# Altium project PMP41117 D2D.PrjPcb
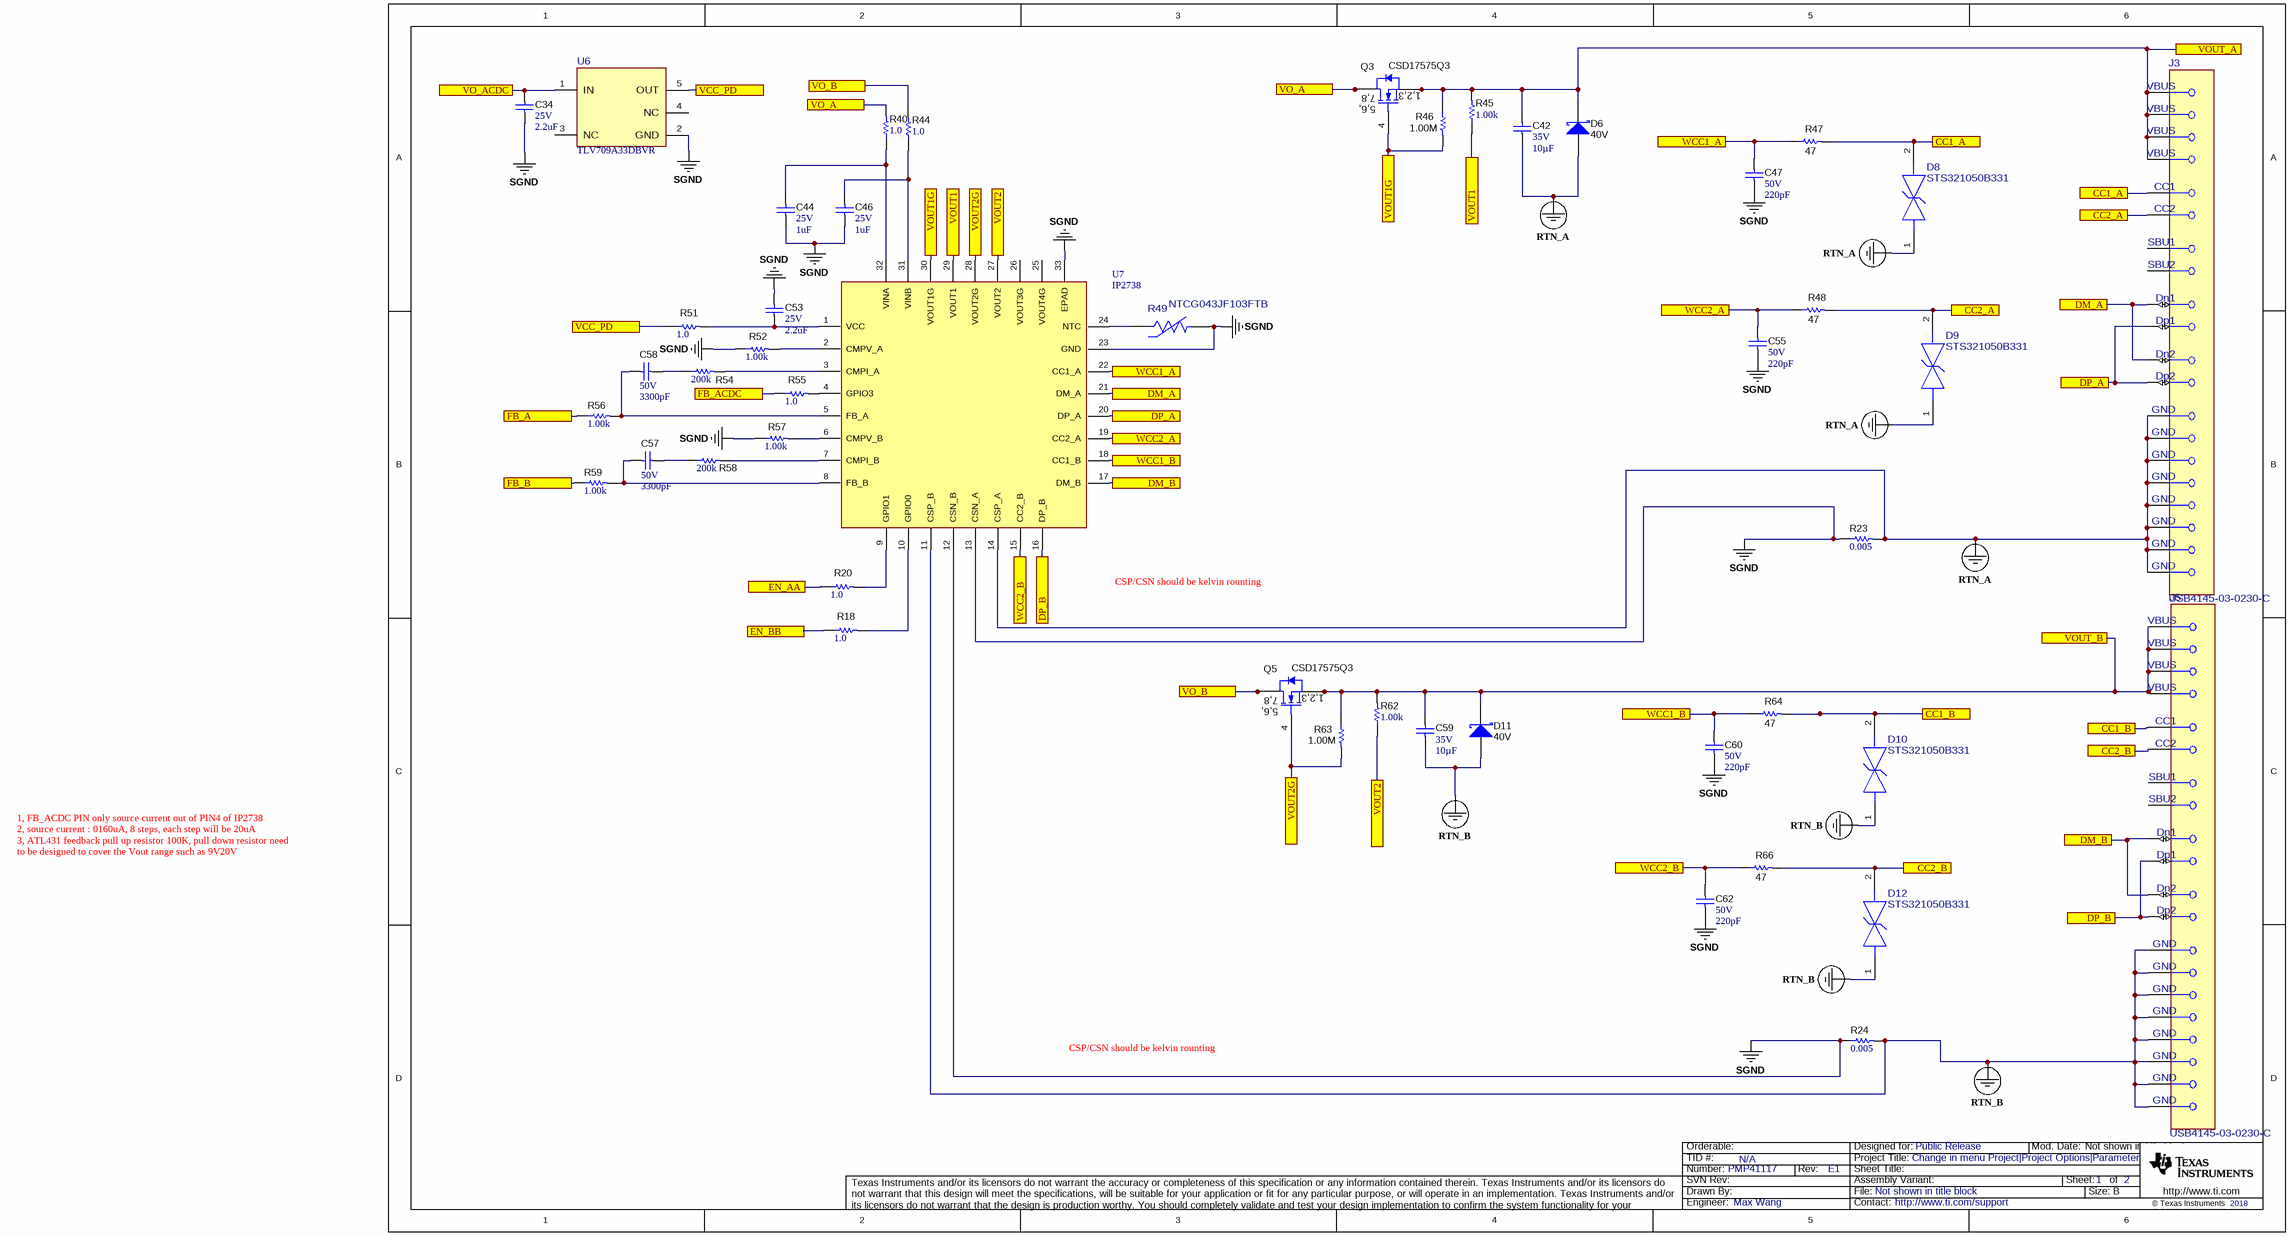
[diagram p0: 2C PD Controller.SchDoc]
CopyrightYear: 2018; PCB_Layout: Max Wang; PCB_Rev: E1; PRJ_Customer: Public Release; PRJ_Engineer: Max Wang; PRJ_Number: PMP41117; PRJ_Title: Change in menu Project|Project Options|Parameters; SCH_Rev: E1; TechSupport: http://www.ti.com/support; TID: N/A
2 sheets, 79 parts. Net scope: flat (ports and power ports of the same name join across sheets).
Board file: PMP41117 DCDC.PcbDoc
Sheets:
  2C PD Controller.SchDoc
  Dual Port DCDC.SchDoc

## Sheet 2C PD Controller.SchDoc
size 431 x 279 mm; Date: Not shown in title block; ApprovedBy: Not shown in title block; CheckedBy: Not shown in title block; Author: Not shown in title block; CompanyName: Not shown in title block; Engineer: Not shown in title block; Organization: Not shown in title block; Address1: Not shown in title block; Address2: Not shown in title block; Address3: Not shown in title block; Address4: Not shown in title block; DocumentNumber: 1; Revision: Use project parameter SCH_Rev; SheetNumber: 1; SheetTotal: 2; PageSetup: Record=PageOptions¦CenterHorizontal=True¦CenterVertical=True¦PrintScale=1.00¦XCorrection=1.00¦YCorrection=1.00¦PrintKind=0¦BorderSize=5000000¦LeftOffset=0¦BottomOffset=0¦Orientation=2¦PaperLength=1000¦PaperWidth=1000¦Scale=100¦PaperSource=15¦PrintQuality=600¦MediaType=1¦DitherType=10¦PaperKind=Letter¦PrintScaleMode=1

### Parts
C34  VDC_V: 25V  ValueDisplayed: 2.2uF  [0402_070]  (hidden comment: GRM155R61E225KE11D)
C42  VDC_V: 35V  ValueDisplayed: 10µF  [0805]  (hidden comment: GMK212BBJ106KG-T)
C44  VDC_V: 25V  ValueDisplayed: 1uF  [0402S]  (hidden comment: GRM155R61E105KA12D)
C46  VDC_V: 25V  ValueDisplayed: 1uF  [0402S]  (hidden comment: GRM155R61E105KA12D)
C47  VDC_V: 50V  ValueDisplayed: 220pF  [0402S]  (hidden comment: GRM155R71H221KA01D)
C53  VDC_V: 25V  ValueDisplayed: 2.2uF  [0402_070]  (hidden comment: GRM155R61E225KE11D)
C55  VDC_V: 50V  ValueDisplayed: 220pF  [0402S]  (hidden comment: GRM155R71H221KA01D)
C57  VDC_V: 50V  ValueDisplayed: 3300pF  [0402S]  (hidden comment: CGA2B2X7R1H332K050BA)
C58  VDC_V: 50V  ValueDisplayed: 3300pF  [0402S]  (hidden comment: CGA2B2X7R1H332K050BA)
C59  VDC_V: 35V  ValueDisplayed: 10µF  [0805]  (hidden comment: GMK212BBJ106KG-T)
C60  VDC_V: 50V  ValueDisplayed: 220pF  [0402S]  (hidden comment: GRM155R71H221KA01D)
C62  VDC_V: 50V  ValueDisplayed: 220pF  [0402S]  (hidden comment: GRM155R71H221KA01D)
D6  value 40V  [SOD-523]  (hidden comment: RB521SM-40T2R)
D8  STS321050B331  [FP-STS321050B331_SOD-323-MFG]
D9  STS321050B331  [FP-STS321050B331_SOD-323-MFG]
D10  STS321050B331  [FP-STS321050B331_SOD-323-MFG]
D11  value 40V  [SOD-523]  (hidden comment: RB521SM-40T2R)
D12  STS321050B331  [FP-STS321050B331_SOD-323-MFG]
J3  USB4145-03-0230-C  [FP-USB4145-03-0230-C_CONN_USB-MFG]
J5  USB4145-03-0230-C  [FP-USB4145-03-0230-C_CONN_USB-MFG]
Q3  CSD17575Q3  [DQG0008A]
Q5  CSD17575Q3  [DQG0008A]
R18  ValueDisplayed: 1.0  [0402S]  (hidden comment: CRCW04021R00JNED)
R20  ValueDisplayed: 1.0  [0402S]  (hidden comment: CRCW04021R00JNED)
R23  ValueDisplayed: 0.005  [WSL0805]  (hidden comment: WSL08055L000FEA)
R24  ValueDisplayed: 0.005  [WSL0805]  (hidden comment: WSL08055L000FEA)
R40  ValueDisplayed: 1.0  [0402S]  (hidden comment: CRCW04021R00JNED)
R44  ValueDisplayed: 1.0  [0402S]  (hidden comment: CRCW04021R00JNED)
R45  ValueDisplayed: 1.00k  [0402S]  (hidden comment: MCR01MZPF1001)
R46  ValueDisplayed: 1.00M  [0402S]  (hidden comment: RMCF0402FT1M00)
R47  ValueDisplayed: 47  [0402S]  (hidden comment: CRCW040247R0JNED)
R48  ValueDisplayed: 47  [0402S]  (hidden comment: CRCW040247R0JNED)
R49  NTCG043JF103FTB  [FP-NTCG043JF103FTB_SMD2-MFG]
R51  ValueDisplayed: 1.0  [0402S]  (hidden comment: CRCW04021R00JNED)
R52  ValueDisplayed: 1.00k  [0402S]  (hidden comment: MCR01MZPF1001)
R54  ValueDisplayed: 200k  [0402S]  (hidden comment: CRCW0402200KFKED)
R55  ValueDisplayed: 1.0  [0402S]  (hidden comment: CRCW04021R00JNED)
R56  ValueDisplayed: 1.00k  [0402S]  (hidden comment: MCR01MZPF1001)
R57  ValueDisplayed: 1.00k  [0402S]  (hidden comment: MCR01MZPF1001)
R58  ValueDisplayed: 200k  [0402S]  (hidden comment: CRCW0402200KFKED)
R59  ValueDisplayed: 1.00k  [0402S]  (hidden comment: MCR01MZPF1001)
R62  ValueDisplayed: 1.00k  [0402S]  (hidden comment: MCR01MZPF1001)
R63  ValueDisplayed: 1.00M  [0402S]  (hidden comment: RMCF0402FT1M00)
R64  ValueDisplayed: 47  [0402S]  (hidden comment: CRCW040247R0JNED)
R66  ValueDisplayed: 47  [0402S]  (hidden comment: CRCW040247R0JNED)
U6  TLV709A33DBVR  [DBV0005A-MFG]
U7  IP2738  [IP2738]

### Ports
CC1_A, CC1_B, CC2_A, CC2_B, DM_A, DM_B, DP_A, DP_B, EN_AA, EN_BB, FB_A, FB_ACDC, FB_B, VCC_PD, VO_A, VO_ACDC, VO_B, VOUT1, VOUT1G, VOUT2, VOUT2G, VOUT_A, VOUT_B, WCC1_A, WCC1_B, WCC2_A, WCC2_B

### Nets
RTN_A: C42.2 D6.2(A) D8.1 D9.1 J3.1(GND) J3.2(GND) J3.3(GND) J3.4(GND) J3.A1(GND) J3.A12(GND) J3.B1(GND) J3.B12(GND) R23.2 U7.14(CSP_A)
RTN_B: C59.2 D10.1 D11.2(A) D12.1 J5.1(GND) J5.2(GND) J5.3(GND) J5.4(GND) J5.A1(GND) J5.A12(GND) J5.B1(GND) J5.B12(GND) R24.2 U7.11(CSP_B)
SGND: C34.2 C44.2 C46.2 C47.2 C53.1 C55.2 C60.2 C62.2 R23.1 R24.1 R49.2 R52.1 R57.1 U6.2(GND) U7.12(CSN_B) U7.13(CSN_A) U7.23(GND) U7.33(EPAD)
CC1_A: D8.2 J3.A5(CC1) R47.2 ; port CC1_A
CC1_B: D10.2 J5.A5(CC1) R64.2 ; port CC1_B
CC2_A: D9.2 J3.B5(CC2) R48.2 ; port CC2_A
CC2_B: D12.2 J5.B5(CC2) R66.2 ; port CC2_B
DM_A: J3.A7(Dn1) J3.B7(Dn2) U7.21(DM_A) ; port DM_A
DM_B: J5.A7(Dn1) J5.B7(Dn2) U7.17(DM_B) ; port DM_B
DP_A: J3.A6(Dp1) J3.B6(Dp2) U7.20(DP_A) ; port DP_A
DP_B: J5.A6(Dp1) J5.B6(Dp2) U7.16(DP_B) ; port DP_B
EN_AA: R20.1 ; port EN_AA
EN_BB: R18.1 ; port EN_BB
FB_A: R56.1 ; port FB_A
FB_ACDC: R55.1 ; port FB_ACDC
FB_B: R59.1 ; port FB_B
VCC_PD: R51.1 U6.5(OUT) ; port VCC_PD
VO_A: Q3.5(D) Q3.6(D) Q3.7(D) Q3.8(D) Q3.9(D) R40.2 ; port VO_A
VO_ACDC: C34.1 U6.1(IN) ; port VO_ACDC
VO_B: Q5.5(D) Q5.6(D) Q5.7(D) Q5.8(D) Q5.9(D) R44.2 ; port VO_B
VOUT1: R45.1 U7.29(VOUT1) ; port VOUT1
VOUT1G: Q3.4(G) R46.2 U7.30(VOUT1G) ; port VOUT1G
VOUT2: R62.1 U7.27(VOUT2) ; port VOUT2
VOUT2G: Q5.4(G) R63.2 U7.28(VOUT2G) ; port VOUT2G
VOUT_A: C42.1 D6.1(K) J3.A4(VBUS) J3.A9(VBUS) J3.B4(VBUS) J3.B9(VBUS) Q3.1(S) Q3.2(S) Q3.3(S) R45.2 R46.1 ; port VOUT_A
VOUT_B: C59.1 D11.1(K) J5.A4(VBUS) J5.A9(VBUS) J5.B4(VBUS) J5.B9(VBUS) Q5.1(S) Q5.2(S) Q5.3(S) R62.2 R63.1 ; port VOUT_B
WCC1_A: C47.1 R47.1 U7.22(CC1_A) ; port WCC1_A
WCC1_B: C60.1 R64.1 U7.18(CC1_B) ; port WCC1_B
WCC2_A: C55.1 R48.1 U7.19(CC2_A) ; port WCC2_A
WCC2_B: C62.1 R66.1 U7.15(CC2_B) ; port WCC2_B
NetC44_1: C44.1 R40.1 U7.32(VINA)
NetC46_1: C46.1 R44.1 U7.31(VINB)
NetC53_2: C53.2 R51.2 U7.1(VCC)
NetC57_1: C57.1 R58.1
NetC57_2: C57.2 R59.2 U7.8(FB_B)
NetC58_1: C58.1 R54.1
NetC58_2: C58.2 R56.2 U7.5(FB_A)
NetR18_2: R18.2 U7.10(GPIO0)
NetR20_2: R20.2 U7.9(GPIO1)
NetR49_1: R49.1 U7.24(NTC)
NetR52_2: R52.2 U7.2(CMPV_A)
NetR54_2: R54.2 U7.3(CMPI_A)
NetR55_2: R55.2 U7.4(GPIO3)
NetR57_2: R57.2 U7.6(CMPV_B)
NetR58_2: R58.2 U7.7(CMPI_B)

Not connected (* = marked no-connect by the designer): J3 A8(SBU1) B8(SBU2); J5 A8(SBU1) B8(SBU2); U6 3(NC) 4(NC); U7 25(VOUT4G) 26(VOUT3G)

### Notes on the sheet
- CSP/CSN should be kelvin rounting
- 1, FB_ACDC PIN only source current out of PIN4 of IP2738
  2, source current : 0160uA, 8 steps, each step will be 20uA
  3, ATL431 feedback pull up resistor 100K, pull down resistor need to be designed to cover the Vout range such as 9V20V

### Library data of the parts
C34 C53 = CMP-0006610-2: CAP, CERM, 2.2 uF, 25 V, +/- 10%, X5R, 0402; Manufacturer: MuRata; TaMin_C: -55°C; Polarized: N; SizeAreaWB_mm2: 3; Value1: Unknown; U/M: EA; Value: 2.2uF; TaMax_C: 85°C; SizeZ_mm: 0.7; SizeX_mm: 1; SizeY_mm: 0.5; Cap_Case: 0402; Cap_F: 2.2µF; AEC Category: Q200
C42 C59 = CMP-0083708-1: CAP, CERM, 10 µF, 35 V,+/- 10%, X5R, 0805; Manufacturer: Taiyo Yuden; SizeAreaWB_mm2: 6.75; SizeArea_mm2: 2.5; AEC Qualified: N; AEC Category: Q200; Value: 10uF; TaMax_C: 85°C; SizeZ_mm: 1.45; TaMin_C: -55°C; SizeY_mm: 1.25; U/M: EA; SizeX_mm: 2
C44 C46 = CMP-0006608-2: CAP, CERM, 1 uF, 25 V, +/- 10%, X5R, 0402; Manufacturer: MuRata; TaMin_C: -55°C; Polarized: N; SizeAreaWB_mm2: 3; Value1: Unknown; U/M: EA; Value: 1uF; TaMax_C: 85°C; SizeZ_mm: 0.6; SizeX_mm: 1; SizeY_mm: 0.5; Cap_Case: 0402; Cap_F: 1µF; AEC Category: Q200
C47 C55 C60 C62 = CMP-0006682-1: CAP, CERM, 220 pF, 50 V, +/- 10%, X7R, 0402; Manufacturer: MuRata; TaMin_C: -55°C; Polarized: N; SizeAreaWB_mm2: 3; Value1: Unknown; U/M: EA; Value: 220pF; TaMax_C: 125°C; SizeZ_mm: 0.6; SizeX_mm: 1; SizeY_mm: 0.5; Cap_Case: 0402; AEC Category: Q200
C57 C58 = CMP-0006319-1: CAP, CERM, 3300 pF, 50 V, +/- 10%, X7R, AEC-Q200 Grade 1, 0402; Manufacturer: TDK; TaMin_C: -55°C; ESR_ohm: 0.7852; Polarized: N; SizeAreaWB_mm2: 3; Value1: 0.785178 ohm; U/M: EA; Value: 3300pF; TaMax_C: 125°C; SizeZ_mm: 0.6; SizeX_mm: 1; SizeY_mm: 0.5; Cap_Case: 0402; AEC Qualified: Y; Cap_F: 3.3nF; IRMS_A: 272.902mA; AEC Category: Q200
D6 D11 = CMP-0074704-3: Diode, Schottky, 40 V, 0.2 A, SOD-523; Manufacturer: Rohm; SizeAreaWB_mm2: 5.13; SizeZ_mm: 0.65; AEC Category: Q101; AEC Qualified: N; Vf_V: 540mV; Io_A: 200mA; Value2: 0.54V; SizeArea_mm2: 1.53; TJmax_C: 150°C; Value1: 0.2A; SizeX_mm: 1.7; SizeY_mm: 0.9
D8-D10 D12 = CMP-0092592-1: 18V Clamp 22A (8/20µs) Ipp Tvs Diode Surface Mount SOD-323; Manufacturer: Eaton; ValueDisplayed: 33pF; Breakdown Voltage: 5.5V; Number Of Channels: 1; SizeZ_mm: 1mm; AEC Qualified: No; Ppk: 400W; VRWM: 5V; TJmax_C: +125°C; Direction: Bidirectional
J3 J5 = CMP-0120965-1: USB Connectors USB-C Rec 3u Vert 16P SMT 2.3mm TH stakes H7.46mm T+R+Cap; Manufacturer: GCT; ContactFinish: Gold,Nickel; Current_A: 6.25A; Shrouded: true; Voltage_V: 48V; AEC Qualified: No; Conn Orientation: Vertical; DUT-Pitch_mm: 0.5mm; Is Female: yes; SizeZ_mm: 7.66mm; Standoff Height: 0.05mm; Usb Standard: USB 2.0
Q3 Q5 = MOSFET_N_D56789G4S123: MOSFET, N-CH, 30 V, 60 A, DQG0008A (VSON-CLIP-8); Manufacturer: Texas Instruments; Alternate Manufacturer: None; U/M: EA; ChType: N; Value: 30V; Value1: 0.003; Rdson45_ohm: 3.2m; Value2: 23 nC; QgTyp_nC: 23; Vgs_V: 20V; IdsMax_A: 60A; AEC Category: Q101; SizeZ_mm: 1.1; SizeX_mm: 3.3; SizeArea_mm2: 10.89; SizeAreaWB_mm2: 18.49
R18 R20 R40 R44 R51 R55 = CMP-0026866-2: RES, 1.0, 5%, 0.063 W, 0402; Manufacturer: Vishay-Dale; Power_W: 63mW; TempCo: 200 ppm/C; Value_Code: 1R00; U/M: EA; Value: 1.0; EIA_Code: E24; Res_ohm: 1; SizeY_mm: 0.5; SizeZ_mm: 0.6; Value2: 0.063W; VDC_V: 50V; AEC Category: Q200
R23 R24 = CMP-0021978-2: RES, 0.005, 1%, 0.25 W, 0805; Manufacturer: Vishay-Dale; Power_W: 250mW; TempCo: 110 ppm/C; Value_Code: 5L000; U/M: EA; Value: 0.005; EIA_Code: E96; Res_ohm: 5m; SizeX_mm: 2.03; SizeY_mm: 1.27; SizeZ_mm: 0.584; Value2: 0.25W; SizeArea_mm2: 2.5781; AEC Qualified: N; AEC Category: Q200
R45 R52 R56 R57 R59 R62 = CMP-0026716-1: RES, 1.00 k, 1%, 0.063 W, 0402; Manufacturer: Rohm; Power_W: 63mW; TempCo: 100 ppm/C; Value_Code: 1k00; U/M: EA; Value: 1.00k; EIA_Code: E96; Res_ohm: 1k; SizeX_mm: 1; SizeY_mm: 0.5; SizeZ_mm: 0.6; Value2: 0.063W; AEC Qualified: N; VDC_V: 50V; AEC Category: Q200
R46 R63 = CMP-0026827-3: RES, 1.00 M, 1%, 0.063 W, AEC-Q200 Grade 0, 0402; Manufacturer: Stackpole Electronics Inc; CompType: Resistor; Value: 1.0Meg; Power_W: 63mW; Value2: 0.063W; VDC_V: 50V; TempCo: 200 ppm/C; SizeArea_mm2: 0.5; SizeX_mm: 1; SizeZ_mm: 0.6; EIA_Code: E24; AEC Category: Q200; AEC Qualified: Y; AEC Grade: 0
R47 R48 R64 R66 = CMP-0026463-2: RES, 47, 5%, 0.063 W, 0402; Manufacturer: Vishay-Dale; Power_W: 63mW; TempCo: 200 ppm/C; Value: 47; EIA_Code: E96; SizeX_mm: 1; SizeY_mm: 0.5; SizeZ_mm: 0.6; Value2: 0.063W; AEC Qualified: Y; VDC_V: 50V; AEC Category: Q200; AEC Grade: 0
R49 = CMP-0095068-1: Chip NTC Thermistors (Sensor), Resistance (at 25°C)=10kΩ, Resistance Tolerance (at 25°C)=±1%; Manufacturer: TDK; SizeZ_mm: 0.22mm; B 25 50: 3380K; Value: 10k; B Tolerance: 1%; B 25 100: 3453K; Res_ohm: 10kΩ; B 25 85: 3435K; AEC Qualified: No
R54 R58 = CMP-0026158-1: RES, 200 k, 1%, 0.063 W, 0402; Manufacturer: Vishay-Dale; Power_W: 63mW; TempCo: 100 ppm/C; U/M: EA; Value: 200k; EIA_Code: E96; SizeX_mm: 1; SizeY_mm: 0.5; SizeZ_mm: 0.6; Value2: 0.063W; VDC_V: 50V; AEC Category: Q200
U6 = CMP-0034271-1: 150-mA 30-V low-dropout (LDO) linear regulator with 3.2-μA supply current 5-SOT-23 -40 to 125; Manufacturer: Texas Instruments; SizeZ_mm: 1.45mm; AEC Qualified: No; Accuracy Percentage: 4%; Dropout Voltage: 1000mV; Max Supply Voltage: 30V; Min Supply Voltage: 4.3V; Nominal Supply Current: 3.2uA; Number Of Outputs: 1; Output Type: Fixed; Output Voltage: 3.3V; Standoff Height: 0mm; TJmax_C: +125°C
U7 = U?: IP2738 dual port USB PD controller; Manufacturer: Injonics

## Sheet Dual Port DCDC.SchDoc
size 431 x 279 mm; Date: Not shown in title block; ApprovedBy: Not shown in title block; CheckedBy: Not shown in title block; Author: Not shown in title block; CompanyName: Not shown in title block; Engineer: Not shown in title block; Organization: Not shown in title block; Address1: Not shown in title block; Address2: Not shown in title block; Address3: Not shown in title block; Address4: Not shown in title block; DocumentNumber: 2; Revision: Use project parameter SCH_Rev; SheetNumber: 2; SheetTotal: 2; PageSetup: Record=PageOptions¦CenterHorizontal=True¦CenterVertical=True¦PrintScale=1.00¦XCorrection=1.00¦YCorrection=1.00¦PrintKind=0¦BorderSize=5000000¦LeftOffset=0¦BottomOffset=0¦Orientation=2¦PaperLength=1000¦PaperWidth=1000¦Scale=100¦PaperSource=15¦PrintQuality=600¦MediaType=1¦DitherType=10¦PaperKind=Letter¦PrintScaleMode=1
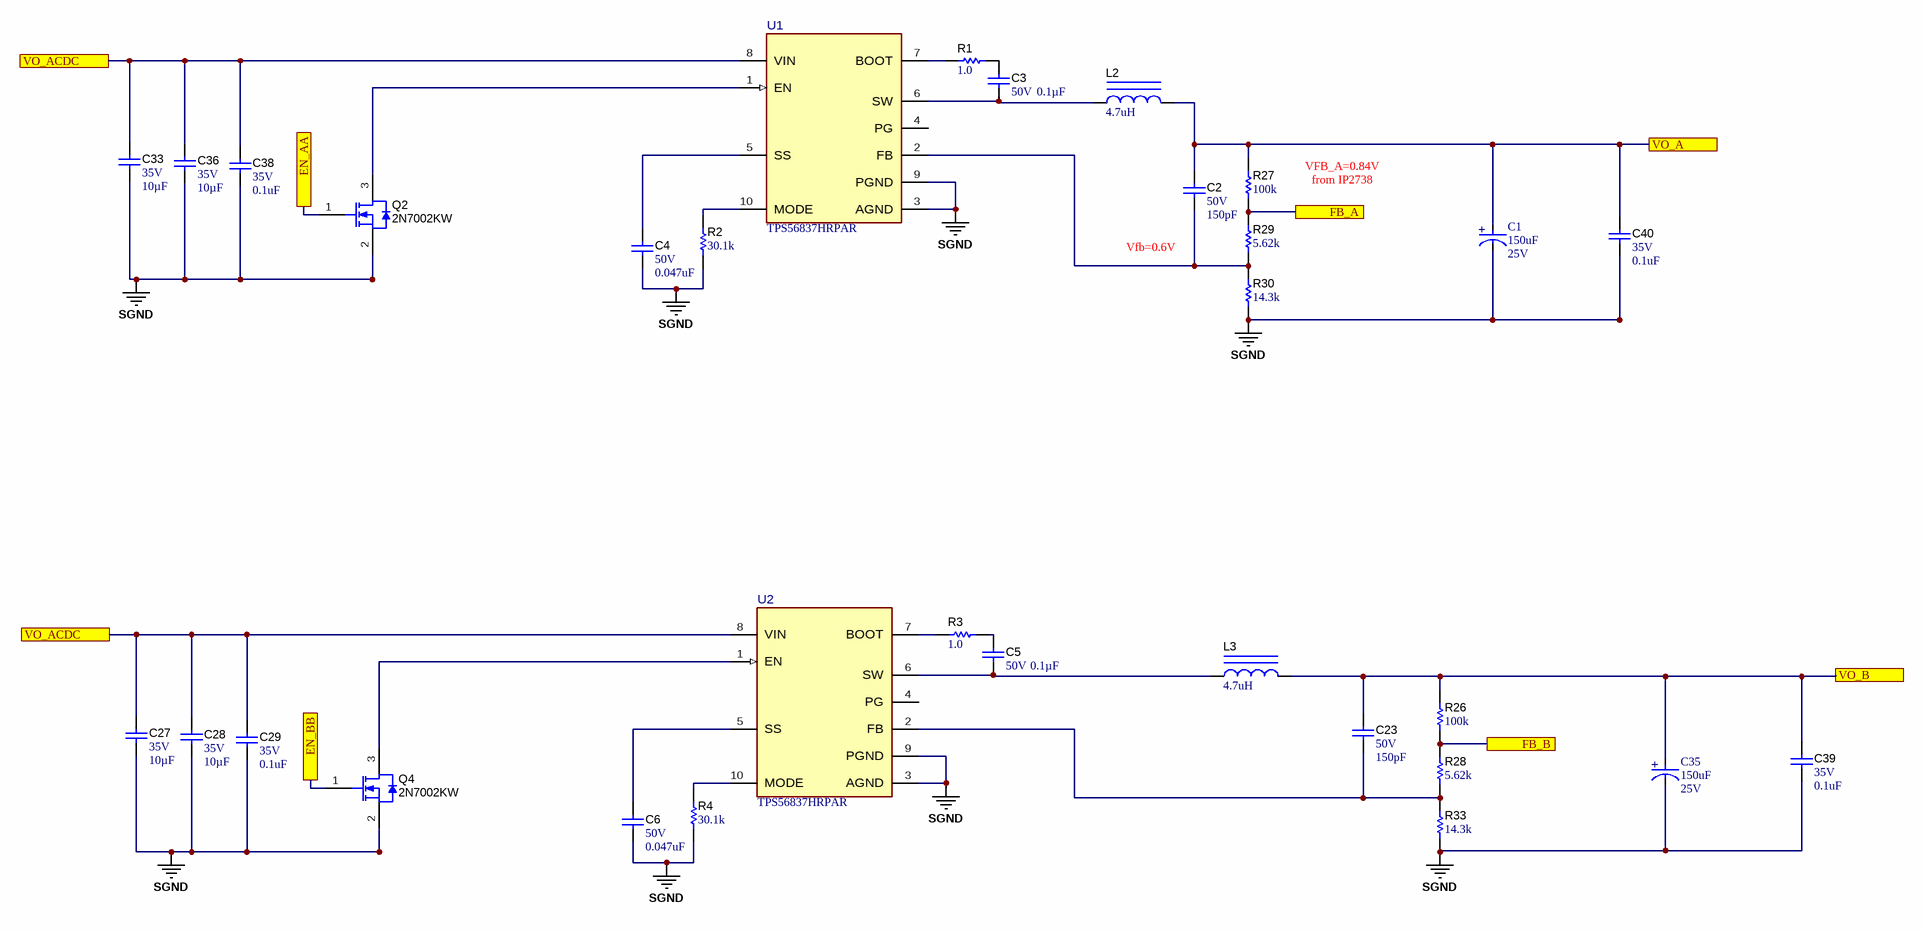
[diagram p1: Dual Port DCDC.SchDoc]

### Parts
C1  value 150uF  Voltage: 25V  [Ecap_5.5_9_2.5]  (hidden comment: CAP 25V 150uF D 5.5X7mm)
C2  VDC_V: 50V  ValueDisplayed: 150pF  [0402S]  (hidden comment: CGA2B2C0G1H151J050BA)
C3  VDC_V: 50V  ValueDisplayed: 0.1µF  [0402S]  (hidden comment: 0402BB104KW500)
C4  VDC_V: 50V  ValueDisplayed: 0.047uF  [0402S]  (hidden comment: C1005X5R1H473K050BB)
C5  VDC_V: 50V  ValueDisplayed: 0.1µF  [0402S]  (hidden comment: 0402BB104KW500)
C6  VDC_V: 50V  ValueDisplayed: 0.047uF  [0402S]  (hidden comment: C1005X5R1H473K050BB)
C23  VDC_V: 50V  ValueDisplayed: 150pF  [0402S]  (hidden comment: CGA2B2C0G1H151J050BA)
C27  VDC_V: 35V  ValueDisplayed: 10µF  [0805_HV]  (hidden comment: GMK212BBJ106KG-T)
C28  VDC_V: 35V  ValueDisplayed: 10µF  [0805_HV]  (hidden comment: GMK212BBJ106KG-T)
C29  VDC_V: 35V  ValueDisplayed: 0.1uF  [0402S]  (hidden comment: GMK105BJ104KV-F)
C33  VDC_V: 35V  ValueDisplayed: 10µF  [0805_HV]  (hidden comment: GMK212BBJ106KG-T)
C35  value 150uF  Voltage: 25V  [Ecap_5.5_9_2.5]  (hidden comment: CAP 25V 150uF D 5.5X7mm)
C36  VDC_V: 35V  ValueDisplayed: 10µF  [0805_HV]  (hidden comment: GMK212BBJ106KG-T)
C38  VDC_V: 35V  ValueDisplayed: 0.1uF  [0402S]  (hidden comment: GMK105BJ104KV-F)
C39  VDC_V: 35V  ValueDisplayed: 0.1uF  [0402S]  (hidden comment: GMK105BJ104KV-F)
C40  VDC_V: 35V  ValueDisplayed: 0.1uF  [0402S]  (hidden comment: GMK105BJ104KV-F)
L2  value 4.7uH  [WE-XHMI_6060]  (hidden comment: Inductor_Iron)
L3  value 4.7uH  [WE-XHMI_6060]  (hidden comment: Inductor_Iron)
Q2  2N7002KW  [SOT-323]
Q4  2N7002KW  [SOT-323]
R1  ValueDisplayed: 1.0  [0402S]  (hidden comment: CRCW04021R00JNED)
R2  ValueDisplayed: 30.1k  [0402S]  (hidden comment: CRCW040230K1FKED)
R3  ValueDisplayed: 1.0  [0402S]  (hidden comment: CRCW04021R00JNED)
R4  ValueDisplayed: 30.1k  [0402S]  (hidden comment: CRCW040230K1FKED)
R26  ValueDisplayed: 100k  [0402S]  (hidden comment: CRCW0402100KDHEDP)
R27  ValueDisplayed: 100k  [0402S]  (hidden comment: CRCW0402100KDHEDP)
R28  ValueDisplayed: 5.62k  [0402S]  (hidden comment: CRCW04025K62FKED)
R29  ValueDisplayed: 5.62k  [0402S]  (hidden comment: CRCW04025K62FKED)
R30  ValueDisplayed: 14.3k  [0402S]  (hidden comment: CRCW040214K3FKED)
R33  ValueDisplayed: 14.3k  [0402S]  (hidden comment: CRCW040214K3FKED)
U1  TPS56837HRPAR  [RPA0010A-MFG]
U2  TPS56837HRPAR  [RPA0010A-MFG]

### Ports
EN_AA, EN_BB, FB_A, FB_B, VO_A, VO_ACDC, VO_B

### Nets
SGND: C1.1(CATHODE) C4.2 C6.2 C27.2 C28.2 C29.2 C33.2 C35.1(CATHODE) C36.2 C38.2 C39.2 C40.2 Q2.2(S) Q4.2(S) R2.1 R4.1 R30.1 R33.1 U1.3(AGND) U1.9(PGND) U2.3(AGND) U2.9(PGND)
EN_AA: Q2.1(G) ; port EN_AA
EN_BB: Q4.1(G) ; port EN_BB
FB_A: R27.1 R29.2 ; port FB_A
FB_B: R26.1 R28.2 ; port FB_B
VO_A: C1.2(ANODE) C2.1 C40.1 L2.2 R27.2 ; port VO_A
VO_ACDC: C27.1 C28.1 C29.1 C33.1 C36.1 C38.1 U1.8(VIN) U2.8(VIN) ; port VO_ACDC
VO_B: C23.1 C35.2(ANODE) C39.1 L3.2 R26.2 ; port VO_B
NetC2_2: C2.2 R29.1 R30.2 U1.2(FB)
NetC3_1: C3.1 R1.2
NetC3_2: C3.2 L2.1 U1.6(SW)
NetC4_1: C4.1 U1.5(SS)
NetC5_1: C5.1 R3.2
NetC5_2: C5.2 L3.1 U2.6(SW)
NetC6_1: C6.1 U2.5(SS)
NetC23_2: C23.2 R28.1 R33.2 U2.2(FB)
NetQ2_3: Q2.3(D) U1.1(EN)
NetQ4_3: Q4.3(D) U2.1(EN)
NetR1_1: R1.1 U1.7(BOOT)
NetR2_2: R2.2 U1.10(MODE)
NetR3_1: R3.1 U2.7(BOOT)
NetR4_2: R4.2 U2.10(MODE)

Not connected (* = marked no-connect by the designer): U1 4(PG); U2 4(PG)

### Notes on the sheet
- VFB_A=0.84V from IP2738
- Vfb=0.6V

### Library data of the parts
C1 C35 = NPXH0701E151MJTM: Manufacturer: Yongming
C2 C23 = CMP-0006310-2: CAP, CERM, 150 pF, 50 V, +/- 5%, C0G/NP0, AEC-Q200 Grade 1, 0402; Manufacturer: TDK; TaMin_C: -55°C; Polarized: N; SizeAreaWB_mm2: 3; Value1: Unknown; U/M: EA; Value: 150pF; TaMax_C: 125°C; SizeZ_mm: 0.6; SizeX_mm: 1; SizeY_mm: 0.5; Cap_Case: 0402; AEC Qualified: Y; AEC Category: Q200
C3 C5 = CMP-0860983-1: CAP, CERM, 0.1 µF, 50 V,+/- 10%, X7R, 0402; Manufacturer: Passive Plus; Cap_Case: 0402; TaMax_C: 125°C; U/M: EA; SizeY_mm: 0.5; TaMin_C: -55°C; SizeAreaWB_mm2: 3; Value: 0.1uF; AEC Qualified: N; SizeX_mm: 1; AEC Category: Q200; SizeZ_mm: 0.6; Cap_F: 100nF
C4 C6 = CMP-0006280-2: CAP, CERM, 0.047 uF, 50 V, +/- 10%, X5R, 0402; Manufacturer: TDK; TaMin_C: -55°C; ESR_ohm: 64.07m; Polarized: N; SizeAreaWB_mm2: 3; Value1: 0.06407 ohm; U/M: EA; TaMax_C: 85°C; SizeZ_mm: 0.6; SizeX_mm: 1; SizeY_mm: 0.5; Cap_Case: 0402; Cap_F: 47nF; IRMS_A: 646.122mA; AEC Category: Q200
C27 C28 C33 C36 = CMP-0083708-1: CAP, CERM, 10 µF, 35 V,+/- 10%, X5R, 0805; Manufacturer: Taiyo Yuden; SizeAreaWB_mm2: 6.75; SizeArea_mm2: 2.5; AEC Qualified: N; AEC Category: Q200; Value: 10uF; TaMax_C: 85°C; SizeZ_mm: 1.45; TaMin_C: -55°C; SizeY_mm: 1.25; U/M: EA; SizeX_mm: 2; Cap_Case: 0805
C29 C38-C40 = CMP-0006370-1: CAP, CERM, 0.1 uF, 35 V, +/- 10%, X5R, 0402; Manufacturer: Taiyo Yuden; TaMin_C: -55°C; Polarized: N; SizeAreaWB_mm2: 3; Value1: Unknown; U/M: EA; Value: 0.1uF; TaMax_C: 85°C; SizeZ_mm: 0.6; SizeX_mm: 1; SizeY_mm: 0.5; Cap_Case: 0402; Cap_F: 100nF; AEC Category: Q200
L2 L3 = Inductor_Iron: Inductor, Shielded,  4.7 µH, 0.01 ohm, SMD XGL6060-472MEC; Manufacturer: Coilcraft; SizeY_mm: 6.45; Value2: 6.9A; Irms: 6.9A @ 40C rise; SizeZ_mm: 6.1; SizeX_mm: 6.65; DCR_ohm: 0.0165; Material: Hyperflux; AEC Qualified: N; SizeArea_mm2: 42.8925; AEC Category: Q200; SizeAreaWB_mm2: 73.0925; Isat: 13.6A @ 30% inductance drop; Value1: 0.0165 ohm
Q2 Q4 = CMP-0000774-1: MOSFET, N-CH, 60 V, 0.31 A, SOT-323; Alternate Manufacturer: None; Manufacturer: Fairchild Semiconductor; SizeZ_mm: 1.1; ChType: N; Value1: 1; VdsMax_V: 60V; SizeX_mm: 2.2; Vgs_V: 2.1V; Value: 60V; Rdson45_ohm: 1.6; SizeArea_mm2: 4.84; AEC Category: Q101; IdsMax_A: 310mA; SizeAreaWB_mm2: 10.24; U/M: EA
R1 R3 = CMP-0026866-2: as R18 on sheet 2C PD Controller
R2 R4 = CMP-0026284-1: RES, 30.1 k, 1%, 0.063 W, 0402; Manufacturer: Vishay-Dale; Power_W: 63mW; TempCo: 100 ppm/C; Value_Code: 30k1; U/M: EA; Value: 30.1k; EIA_Code: E96; SizeX_mm: 1; SizeY_mm: 0.5; SizeZ_mm: 0.6; Value2: 0.063W; VDC_V: 50V; AEC Category: Q200
R26 R27 = CMP-0026768-1: RES, 100 k, 0.5%, 0.063 W, 0402; Manufacturer: Vishay-Dale; Power_W: 63mW; TempCo: 50 ppm/C; U/M: EA; Value: 100k; EIA_Code: E192; SizeX_mm: 1; SizeY_mm: 0.5; SizeZ_mm: 0.6; Value2: 0.063W; VDC_V: 50V; AEC Category: Q200
R28 R29 = CMP-0026467-2: RES, 5.62 k, 1%, 0.063 W, AEC-Q200 Grade 0, 0402; Manufacturer: Vishay-Dale; Power_W: 63mW; TempCo: 100 ppm/C; Value_Code: 5k62; Value: 5.62k; EIA_Code: E96; SizeX_mm: 1; SizeY_mm: 0.5; SizeZ_mm: 0.6; Value2: 0.063W; AEC Qualified: Y; VDC_V: 50V; AEC Category: Q200; AEC Grade: 0
R30 R33 = CMP-0026016-3: RES, 14.3 k, 1%, 0.063 W, AEC-Q200 Grade 0, 0402; Manufacturer: Vishay-Dale; Power_W: 63mW; TempCo: 100 ppm/C; Value_Code: 14k3; Value: 14.3k; EIA_Code: E96; SizeX_mm: 1; SizeY_mm: 0.5; SizeZ_mm: 0.6; Value2: 0.063W; AEC Qualified: Y; VDC_V: 50V; AEC Category: Q200; AEC Grade: 0
U1 U2 = CMP-0097667-3: 4.5-V to 28-V Input, 8-A Synchronous Buck Converter; Manufacturer: Texas Instruments; Switching Frequency: 500/800/1200kHz; SizeZ_mm: 1mm; Min Supply Voltage: 4.5V; Nominal Supply Current: 50uA; Output Type: AdjustableProgrammable; AEC Qualified: No; Max Supply Voltage: 28V; Standoff Height: 0mm; Output Voltage: 0.6-13V; TJmax_C: +150°C; Max Duty Cycle: 98%; Number Of Outputs: 1; AEC Category: Q200; CompType: IC

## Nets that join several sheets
SGND: 2C PD Controller (18 pins), Dual Port DCDC (22 pins)
EN_AA: 2C PD Controller (R20.1), Dual Port DCDC (Q2.1)
EN_BB: 2C PD Controller (R18.1), Dual Port DCDC (Q4.1)
FB_A: 2C PD Controller (R56.1), Dual Port DCDC (R27.1 R29.2)
FB_B: 2C PD Controller (R59.1), Dual Port DCDC (R26.1 R28.2)
VO_A: 2C PD Controller (6 pins), Dual Port DCDC (5 pins)
VO_ACDC: 2C PD Controller (C34.1 U6.1), Dual Port DCDC (8 pins)
VO_B: 2C PD Controller (6 pins), Dual Port DCDC (5 pins)

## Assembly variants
001: not fitted FID1 FID2 FID3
